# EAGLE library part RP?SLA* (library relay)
Special Load PCB Relay SCHRACK 1 pole 16 A, for high inrush currents, monostable Source: http://www.schrack.com/.. 5837.pdf
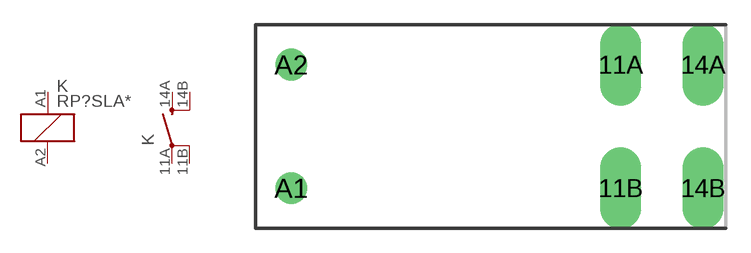
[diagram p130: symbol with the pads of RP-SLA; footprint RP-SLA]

Designator prefix K; gates 1=K 2=S-X2

## RP3SLA05 (MF: TYCO ELECTRONICS; MPN: RP3SLA05; OC_FARNELL: unknown; OC_NEWARK: 08H3553), RP3SLA12 (MF: TYCO ELECTRONICS; MPN: RP3SLA12; OC_FARNELL: unknown; OC_NEWARK: 08H3554), RP3SLA24 (MF: TYCO ELECTRONICS; MPN: RP3SLA24; OC_FARNELL: unknown; OC_NEWARK: 08H3555)  [RP-SLA]
11A  2:PA  pas
11B  2:PB  pas
14A  2:SA  pas
14B  2:SB  pas
A1  1:1  pas
A2  1:2  pas

## RP7SLA05 (OC_FARNELL: unknown; OC_NEWARK: unknown), RP7SLA12 (MF: TYCO ELECTRONICS; MPN: 6-1393231-4; OC_FARNELL: unknown; OC_NEWARK: 16H0754), RP7SLA24 (OC_FARNELL: unknown; OC_NEWARK: unknown)  [RP-SLA]
Pads as for RP-SLA

## Footprint RP-SLA (pad centres in mm)
Special Load PCB Relay SCHRACK 1 pole 16 A, for high inrush currents, monostable Source: http://www.schrack.com/.. 5837.pdf
drill 1.3 pad 2.5 long: 11A 7.56,3.78; 11B 7.56,-3.78; 14A 12.6,3.78; 14B 12.6,-3.78
drill 1.3 round: A1 -12.6,-3.78; A2 -12.6,3.78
